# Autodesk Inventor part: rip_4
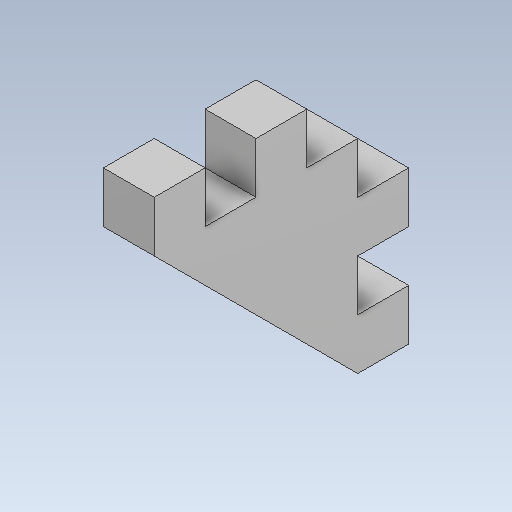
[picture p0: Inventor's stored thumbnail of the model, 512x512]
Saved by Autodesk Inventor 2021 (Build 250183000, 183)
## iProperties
Created: 2026-10
Part Number: rip_4
Material: Steel
Document SubType Name: Modeling
Designer: hp
Density: 7.85 g/cm^3
Appearance: Default
Author: hp
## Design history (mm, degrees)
feature "Body1"
body "Solid1"
